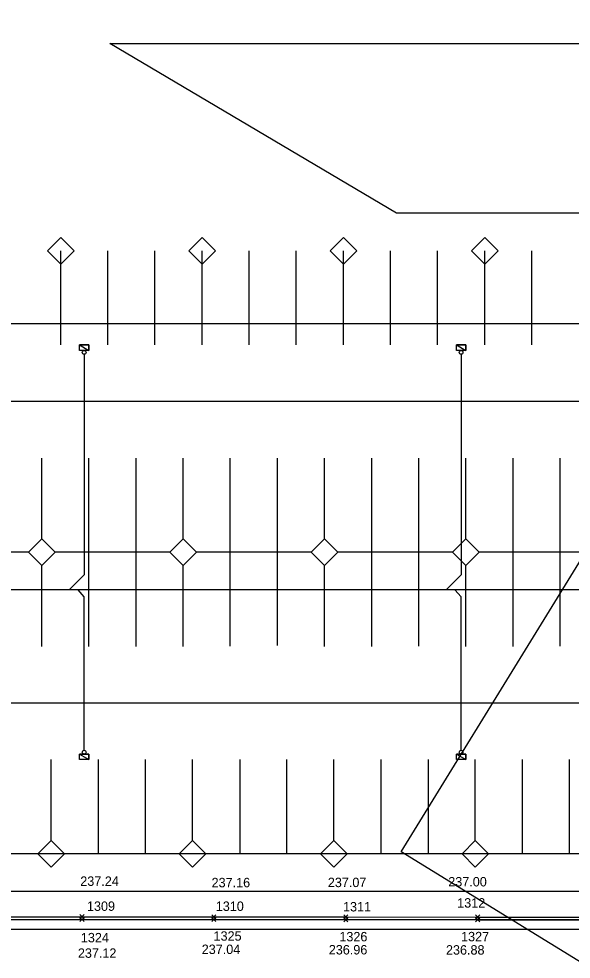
# Model space of a CAD drawing. Extents: x -264205 to -263615, y -1242401 to -1242031.
# Drawn here: x -263854.29 to -263824.98, y -1242303.58 to -1242253.67 of the extents above; entities that cross this region are included whole.
import ezdxf

# ---------------------------------------------------------------- set-up
doc = ezdxf.new("R2010")
doc.units = 0
for name, color, linetype in [('BODY_SYMBOL A CISLO_2-1', 7, 'Continuous'), ('BODY_VYSKA_2-1', 7, 'Continuous'), ('KOORDINACNA_SITUACIA_DSP', 7, 'Continuous'), ('PROJEKT_DRS_TDZ_VODOROVNE', 7, 'Continuous'), ('RAM_NA_TLAC_1-250_SITUACIA_2-1', 7, 'Continuous'), ('RAM_NA_TLAC_1-250_SITUACIA_2-2', 7, 'Continuous'), ('SO_20-1_OBRUBNIKY_DOLNA_HRANA', 7, 'Continuous'), ('SO_20-1_OBRUBNIKY_HORNA_HRANA', 7, 'Continuous')]:
    doc.layers.add(name, color=color, linetype=linetype)

msp = doc.modelspace()

# ---------------------------------------------------------------- linework, layer by layer
at = {"layer": 'BODY_SYMBOL A CISLO_2-1'}
for p, q in [((-263851.052, -1242301.582), (-263850.83, -1242301.36)), ((-263850.83, -1242301.582), (-263851.052, -1242301.36)), ((-263851.046, -1242301.434), (-263850.824, -1242301.214)), ((-263850.824, -1242301.434), (-263851.046, -1242301.214)), ((-263844.057, -1242301.582), (-263843.837, -1242301.36)), ((-263843.837, -1242301.582), (-263844.057, -1242301.36)), ((-263844.052, -1242301.441), (-263843.83, -1242301.221)), ((-263843.83, -1242301.441), (-263844.052, -1242301.221)), ((-263837.052, -1242301.592), (-263836.831, -1242301.37)), ((-263836.831, -1242301.592), (-263837.052, -1242301.37)), ((-263837.05, -1242301.443), (-263836.829, -1242301.221)), ((-263836.829, -1242301.443), (-263837.05, -1242301.221)), ((-263830.054, -1242301.595), (-263829.833, -1242301.373)), ((-263829.833, -1242301.595), (-263830.054, -1242301.373)), ((-263830.052, -1242301.453), (-263829.83, -1242301.231)), ((-263829.83, -1242301.453), (-263830.052, -1242301.231))]:
    msp.add_line(p, q, dxfattribs=at)
at = {"layer": 'KOORDINACNA_SITUACIA_DSP'}
for p, q in [((-263851.074, -1242270.983), (-263850.574, -1242270.983)), ((-263851.074, -1242271.273), (-263851.074, -1242270.983)), ((-263851.074, -1242270.983), (-263850.574, -1242271.273)), ((-263851.074, -1242270.983), (-263850.574, -1242271.273)), ((-263850.574, -1242270.983), (-263851.074, -1242270.983)), ((-263850.574, -1242270.983), (-263850.574, -1242271.273)), ((-263850.574, -1242271.273), (-263850.574, -1242270.983)), ((-263831.074, -1242270.983), (-263830.574, -1242270.983)), ((-263831.074, -1242271.273), (-263831.074, -1242270.983)), ((-263831.074, -1242270.983), (-263830.574, -1242271.273)), ((-263831.074, -1242270.983), (-263830.574, -1242271.273)), ((-263830.574, -1242270.983), (-263831.074, -1242270.983)), ((-263830.574, -1242270.983), (-263830.574, -1242271.273)), ((-263830.574, -1242271.273), (-263830.574, -1242270.983)), ((-263850.574, -1242271.273), (-263851.074, -1242271.273)), ((-263850.824, -1242271.473), (-263850.824, -1242283.187)), ((-263830.574, -1242271.273), (-263831.074, -1242271.273)), ((-263830.824, -1242271.473), (-263830.824, -1242283.187)), ((-263850.824, -1242283.187), (-263851.619, -1242283.982)), ((-263830.824, -1242283.187), (-263831.619, -1242283.982)), ((-263817.941, -1242283.982), (-263870.324, -1242283.982)), ((-263817.941, -1242283.982), (-263870.324, -1242283.982)), ((-263850.824, -1242284.343), (-263851.149, -1242283.982)), ((-263830.824, -1242284.343), (-263831.149, -1242283.982)), ((-263850.824, -1242292.492), (-263850.824, -1242284.343)), ((-263830.824, -1242292.492), (-263830.824, -1242284.343)), ((-263851.074, -1242292.693), (-263850.574, -1242292.693)), ((-263851.074, -1242292.983), (-263851.074, -1242292.693)), ((-263851.074, -1242292.693), (-263850.574, -1242292.983)), ((-263851.074, -1242292.693), (-263850.574, -1242292.983)), ((-263850.574, -1242292.693), (-263851.074, -1242292.693)), ((-263850.574, -1242292.983), (-263851.074, -1242292.983)), ((-263850.574, -1242292.693), (-263850.574, -1242292.983)), ((-263850.574, -1242292.983), (-263850.574, -1242292.693)), ((-263831.074, -1242292.693), (-263830.574, -1242292.693)), ((-263831.074, -1242292.983), (-263831.074, -1242292.693)), ((-263831.074, -1242292.693), (-263830.574, -1242292.983)), ((-263831.074, -1242292.693), (-263830.574, -1242292.983)), ((-263830.574, -1242292.693), (-263831.074, -1242292.693)), ((-263830.574, -1242292.983), (-263831.074, -1242292.983)), ((-263830.824, -1242292.693), (-263830.824, -1242292.692)), ((-263830.574, -1242292.693), (-263830.574, -1242292.983)), ((-263830.574, -1242292.983), (-263830.574, -1242292.693)), ((-263815.601, -1242297.982), (-263917.08, -1242297.982)), ((-263816.308, -1242299.982), (-263918.049, -1242299.982)), ((-263914.08, -1242301.482), (-263815.822, -1242301.482))]:
    msp.add_line(p, q, dxfattribs=at)
for points in [[(-263802.068, -1242263.988), (-263834.256, -1242263.984), (-263849.468, -1242254.985), (-263802.068, -1242254.987)], [(-263852.068, -1242265.279), (-263851.361, -1242265.986), (-263852.068, -1242266.693), (-263852.775, -1242265.986)], [(-263844.568, -1242265.279), (-263843.861, -1242265.986), (-263844.568, -1242266.693), (-263845.275, -1242265.986)], [(-263837.068, -1242265.279), (-263836.361, -1242265.986), (-263837.068, -1242266.693), (-263837.775, -1242265.986)], [(-263829.568, -1242265.279), (-263828.861, -1242265.986), (-263829.568, -1242266.693), (-263830.275, -1242265.986)], [(-263853.068, -1242281.275), (-263852.361, -1242281.982), (-263853.068, -1242282.689), (-263853.775, -1242281.982)], [(-263845.568, -1242281.275), (-263844.861, -1242281.982), (-263845.568, -1242282.689), (-263846.275, -1242281.982)], [(-263838.068, -1242281.275), (-263837.361, -1242281.982), (-263838.068, -1242282.689), (-263838.775, -1242281.982)], [(-263830.568, -1242281.275), (-263829.861, -1242281.982), (-263830.568, -1242282.689), (-263831.275, -1242281.982)], [(-263852.568, -1242297.275), (-263851.861, -1242297.982), (-263852.568, -1242298.689), (-263853.275, -1242297.982)], [(-263845.068, -1242297.275), (-263844.361, -1242297.982), (-263845.068, -1242298.689), (-263845.775, -1242297.982)], [(-263837.568, -1242297.275), (-263836.861, -1242297.982), (-263837.568, -1242298.689), (-263838.275, -1242297.982)], [(-263830.068, -1242297.275), (-263829.361, -1242297.982), (-263830.068, -1242298.689), (-263830.775, -1242297.982)]]:
    msp.add_lwpolyline(points, close=True, dxfattribs=at)
for centre in [(-263850.824, -1242271.373), (-263830.824, -1242271.373), (-263850.824, -1242292.592), (-263830.824, -1242292.592)]:
    msp.add_circle(centre, 0.1, dxfattribs=at)
at = {"layer": 'PROJEKT_DRS_TDZ_VODOROVNE'}
for p, q in [((-263852.068, -1242270.982), (-263852.068, -1242265.982)), ((-263849.568, -1242270.982), (-263849.568, -1242265.982)), ((-263847.068, -1242270.982), (-263847.068, -1242265.982)), ((-263844.568, -1242270.982), (-263844.568, -1242265.982)), ((-263842.068, -1242270.982), (-263842.068, -1242265.982)), ((-263839.568, -1242270.982), (-263839.568, -1242265.982)), ((-263837.068, -1242270.982), (-263837.068, -1242265.982)), ((-263834.568, -1242270.982), (-263834.568, -1242265.982)), ((-263832.068, -1242270.982), (-263832.068, -1242265.982)), ((-263829.568, -1242270.982), (-263829.568, -1242265.982)), ((-263827.068, -1242270.982), (-263827.068, -1242265.982)), ((-263817.068, -1242273.982), (-263917.477, -1242273.982)), ((-263853.068, -1242281.275), (-263853.068, -1242276.982)), ((-263850.568, -1242281.982), (-263850.568, -1242276.982)), ((-263848.068, -1242281.982), (-263848.068, -1242276.982)), ((-263845.568, -1242281.275), (-263845.568, -1242276.982)), ((-263843.068, -1242281.982), (-263843.068, -1242276.982)), ((-263840.568, -1242281.982), (-263840.568, -1242276.982)), ((-263838.068, -1242281.275), (-263838.068, -1242276.982)), ((-263835.568, -1242281.982), (-263835.568, -1242276.982)), ((-263833.068, -1242281.982), (-263833.068, -1242276.982)), ((-263830.568, -1242281.275), (-263830.568, -1242276.982)), ((-263828.068, -1242282.482), (-263828.068, -1242276.982)), ((-263825.568, -1242282.482), (-263825.568, -1242276.982)), ((-263853.775, -1242281.982), (-263859.861, -1242281.982)), ((-263846.275, -1242281.982), (-263852.361, -1242281.982)), ((-263850.568, -1242286.982), (-263850.568, -1242281.982)), ((-263848.068, -1242286.982), (-263848.068, -1242281.982)), ((-263838.775, -1242281.982), (-263844.861, -1242281.982)), ((-263843.068, -1242286.976), (-263843.068, -1242281.982)), ((-263840.568, -1242286.929), (-263840.568, -1242281.982)), ((-263831.275, -1242281.982), (-263837.361, -1242281.982)), ((-263835.568, -1242286.982), (-263835.568, -1242281.982)), ((-263833.068, -1242286.976), (-263833.068, -1242281.982)), ((-263823.775, -1242281.982), (-263829.861, -1242281.982)), ((-263828.068, -1242286.982), (-263828.068, -1242281.982)), ((-263825.568, -1242286.976), (-263825.568, -1242281.982)), ((-263853.068, -1242286.982), (-263853.068, -1242282.689)), ((-263845.568, -1242286.982), (-263845.568, -1242282.689)), ((-263838.068, -1242286.982), (-263838.068, -1242282.689)), ((-263830.568, -1242286.982), (-263830.568, -1242282.689)), ((-263819.531, -1242289.994), (-263917.477, -1242289.994)), ((-263852.568, -1242297.275), (-263852.568, -1242292.982)), ((-263850.068, -1242297.982), (-263850.068, -1242292.982)), ((-263847.568, -1242297.982), (-263847.568, -1242292.982)), ((-263845.068, -1242297.275), (-263845.068, -1242292.982)), ((-263842.568, -1242292.982), (-263842.568, -1242297.982)), ((-263840.068, -1242297.982), (-263840.068, -1242292.982)), ((-263837.568, -1242297.275), (-263837.568, -1242292.982)), ((-263835.068, -1242297.982), (-263835.068, -1242292.982)), ((-263832.568, -1242292.982), (-263832.568, -1242297.982)), ((-263830.068, -1242297.275), (-263830.068, -1242292.982)), ((-263827.568, -1242297.982), (-263827.568, -1242292.982)), ((-263825.068, -1242297.982), (-263825.068, -1242292.982)), ((-263913.857, -1242301.982), (-263816.374, -1242301.982))]:
    msp.add_line(p, q, dxfattribs=at)
at = {"layer": 'RAM_NA_TLAC_1-250_SITUACIA_2-1'}
msp.add_lwpolyline([(-264151.333, -1242269.835), (-263718.833, -1242269.835), (-263718.833, -1242344.085), (-264151.333, -1242344.085)], close=True, dxfattribs=at)
at = {"layer": 'RAM_NA_TLAC_1-250_SITUACIA_2-2'}
msp.add_lwpolyline([(-263834.004, -1242297.889), (-263756.71, -1242172.264), (-263693.471, -1242211.173), (-263770.766, -1242336.799)], close=True, dxfattribs=at)
at = {"layer": 'SO_20-1_OBRUBNIKY_DOLNA_HRANA'}
msp.add_lwpolyline([(-263913.884, -1242301.489), (-263907.893, -1242301.489), (-263900.89, -1242301.488), (-263893.898, -1242301.483), (-263886.917, -1242301.473), (-263879.922, -1242301.465), (-263872.91, -1242301.469), (-263865.929, -1242301.465), (-263859.932, -1242301.473), (-263850.941, -1242301.471), (-263843.947, -1242301.471), (-263836.942, -1242301.481), (-263829.943, -1242301.484), (-263823.945, -1242301.487), (-263818.452, -1242301.495), (-263816.42, -1242301.504)], dxfattribs=at)
at = {"layer": 'SO_20-1_OBRUBNIKY_HORNA_HRANA'}
msp.add_lwpolyline([(-263913.884, -1242301.344), (-263907.893, -1242301.343), (-263900.896, -1242301.344), (-263893.895, -1242301.338), (-263886.916, -1242301.328), (-263879.921, -1242301.324), (-263872.911, -1242301.324), (-263865.928, -1242301.325), (-263859.931, -1242301.327), (-263850.935, -1242301.324), (-263843.941, -1242301.331), (-263836.939, -1242301.332), (-263829.941, -1242301.342), (-263823.94, -1242301.343), (-263818.456, -1242301.352), (-263816.413, -1242301.358)], dxfattribs=at)

# ---------------------------------------------------------------- texts
at = {"layer": 'BODY_SYMBOL A CISLO_2-1'}
for s, p in [('1312', (-263831.03, -1242300.843)), ('1309', (-263850.674, -1242301.017)), ('1310', (-263843.839, -1242301.018)), ('1311', (-263837.088, -1242301.046)), ('1324', (-263850.998, -1242302.688)), ('1325', (-263843.958, -1242302.6)), ('1326', (-263837.282, -1242302.635)), ('1327', (-263830.824, -1242302.632))]:
    msp.add_text(s, height=0.5, dxfattribs=at).set_placement(p)
at = {"layer": 'BODY_VYSKA_2-1'}
for s, p in [('237.24', (-263851.029, -1242299.69)), ('237.16', (-263844.061, -1242299.765)), ('237.07', (-263837.894, -1242299.755)), ('237.00', (-263831.504, -1242299.72)), ('237.04', (-263844.585, -1242303.306)), ('236.96', (-263837.843, -1242303.329)), ('236.88', (-263831.626, -1242303.338)), ('237.12', (-263851.156, -1242303.508))]:
    msp.add_text(s, height=0.5, dxfattribs=at).set_placement(p)

doc.saveas('drawing.dxf')
